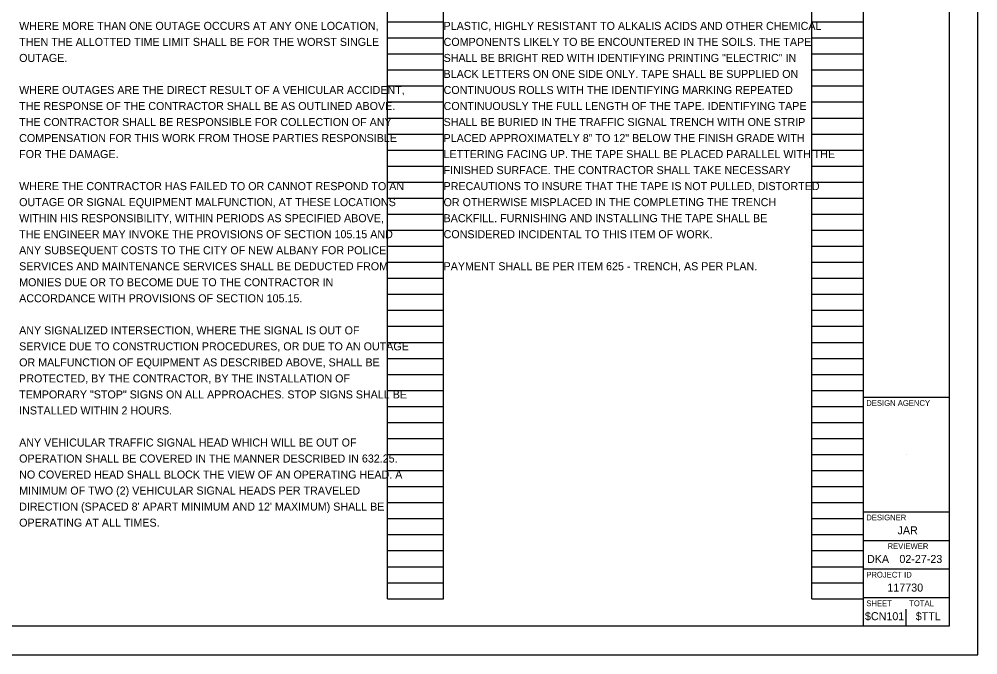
# Model space of a CAD drawing. Extents: x 0 to 34, y 0 to 22.
# Drawn here: x 17.24 to 34, y 0 to 11.11 of the extents above; entities that cross this region are included whole.
import ezdxf

# ---------------------------------------------------------------- set-up
doc = ezdxf.new("R2010")
doc.units = 0
for name, color, linetype in [('SH_Border', 7, 'Continuous'), ('SH_Cut_Line', 7, 'Continuous'), ('SH_Data', 7, 'Continuous'), ('SH_Text', 7, 'Continuous')]:
    doc.layers.add(name, color=color, linetype=linetype)

msp = doc.modelspace()

# ---------------------------------------------------------------- linework, layer by layer
at = {"layer": 'SH_Border'}
for p, q in [((32, 0.5), (32, 21.5)), ((32, 4.5), (33.5, 4.5)), ((32, 2.5), (33.5, 2.5)), ((32, 2), (33.5, 2)), ((32, 1.5), (33.5, 1.5)), ((32, 1), (33.5, 1))]:
    msp.add_line(p, q, dxfattribs=at)
msp.add_lwpolyline([(1.5, 21.5), (33.5, 21.5), (33.5, 0.5), (1.5, 0.5)], close=True, dxfattribs=at)
at = {"layer": 'SH_Cut_Line'}
msp.add_lwpolyline([(0, 0), (34, 0), (34, 22), (0, 22)], close=True, dxfattribs=at)
at = {"layer": 'SH_Data'}
for p, q in [((23.68, 0.98), (23.68, 21.14)), ((24.66, 0.98), (24.66, 21.14)), ((31.1, 0.98), (31.1, 21.14)), ((32, 0.98), (32, 21.14)), ((23.68, 11.06), (24.66, 11.06)), ((31.1, 11.06), (32, 11.06)), ((23.68, 10.78), (24.66, 10.78)), ((31.1, 10.78), (32, 10.78)), ((23.68, 10.5), (24.66, 10.5)), ((31.1, 10.5), (32, 10.5)), ((23.68, 10.22), (24.66, 10.22)), ((31.1, 10.22), (32, 10.22)), ((23.68, 9.94), (24.66, 9.94)), ((31.1, 9.94), (32, 9.94)), ((23.68, 9.66), (24.66, 9.66)), ((31.1, 9.66), (32, 9.66)), ((23.68, 9.38), (24.66, 9.38)), ((31.1, 9.38), (32, 9.38)), ((23.68, 9.1), (24.66, 9.1)), ((31.1, 9.1), (32, 9.1)), ((23.68, 8.82), (24.66, 8.82)), ((31.1, 8.82), (32, 8.82)), ((23.68, 8.54), (24.66, 8.54)), ((31.1, 8.54), (32, 8.54)), ((23.68, 8.26), (24.66, 8.26)), ((31.1, 8.26), (32, 8.26)), ((23.68, 7.98), (24.66, 7.98)), ((31.1, 7.98), (32, 7.98)), ((23.68, 7.7), (24.66, 7.7)), ((31.1, 7.7), (32, 7.7)), ((23.68, 7.42), (24.66, 7.42)), ((31.1, 7.42), (32, 7.42)), ((23.68, 7.14), (24.66, 7.14)), ((31.1, 7.14), (32, 7.14)), ((23.68, 6.86), (24.66, 6.86)), ((31.1, 6.86), (32, 6.86)), ((23.68, 6.58), (24.66, 6.58)), ((31.1, 6.58), (32, 6.58)), ((23.68, 6.3), (24.66, 6.3)), ((31.1, 6.3), (32, 6.3)), ((23.68, 6.02), (24.66, 6.02)), ((31.1, 6.02), (32, 6.02)), ((23.68, 5.74), (24.66, 5.74)), ((31.1, 5.74), (32, 5.74)), ((23.68, 5.46), (24.66, 5.46)), ((31.1, 5.46), (32, 5.46)), ((23.68, 5.18), (24.66, 5.18)), ((31.1, 5.18), (32, 5.18)), ((23.68, 4.9), (24.66, 4.9)), ((31.1, 4.9), (32, 4.9)), ((23.68, 4.62), (24.66, 4.62)), ((31.1, 4.62), (32, 4.62)), ((23.68, 4.34), (24.66, 4.34)), ((31.1, 4.34), (32, 4.34)), ((23.68, 4.06), (24.66, 4.06)), ((31.1, 4.06), (32, 4.06)), ((23.68, 3.78), (24.66, 3.78)), ((31.1, 3.78), (32, 3.78)), ((23.68, 3.5), (24.66, 3.5)), ((31.1, 3.5), (32, 3.5)), ((32.75, 3.5), (32.75, 3.5)), ((23.68, 3.22), (24.66, 3.22)), ((31.1, 3.22), (32, 3.22)), ((23.68, 2.94), (24.66, 2.94)), ((31.1, 2.94), (32, 2.94)), ((23.68, 2.66), (24.66, 2.66)), ((31.1, 2.66), (32, 2.66)), ((23.68, 2.38), (24.66, 2.38)), ((31.1, 2.38), (32, 2.38)), ((23.68, 2.1), (24.66, 2.1)), ((31.1, 2.1), (32, 2.1)), ((23.68, 1.82), (24.66, 1.82)), ((31.1, 1.82), (32, 1.82)), ((23.68, 1.54), (24.66, 1.54)), ((31.1, 1.54), (32, 1.54)), ((23.68, 1.26), (24.66, 1.26)), ((31.1, 1.26), (32, 1.26)), ((23.68, 0.98), (24.66, 0.98)), ((31.1, 0.98), (32, 0.98)), ((32.375, 0.675), (32.375, 0.675)), ((32.75, 0.5), (32.75, 0.8))]:
    msp.add_line(p, q, dxfattribs=at)

# ---------------------------------------------------------------- texts
for s, height, p in [('DESIGN AGENCY', 0.1, (32.05, 4.35)), ('DESIGNER', 0.1, (32.05, 2.35)), ('JAR', 0.14, (32.597, 2.105)), ('REVIEWER', 0.1, (32.422, 1.85)), ('DKA', 0.14, (32.063, 1.605)), ('02-27-23', 0.14, (32.629, 1.605)), ('PROJECT ID', 0.1, (32.05, 1.35)), ('117730', 0.14, (32.419, 1.105)), ('SHEET', 0.1, (32.05, 0.85)), ('TOTAL', 0.1, (32.8, 0.85)), ('$CN101', 0.14, (32.027, 0.605)), ('$TTL', 0.14, (32.915, 0.605))]:
    msp.add_text(s, height=height, dxfattribs=at).set_placement(p)
at = {"layer": 'SH_Text'}
for s, p in [('WHERE MORE THAN ONE OUTAGE OCCURS AT ANY ONE LOCATION, ', (17.24, 10.92)), ('PLASTIC, HIGHLY RESISTANT TO ALKALIS ACIDS AND OTHER CHEMICAL ', (24.66, 10.92)), ('THEN THE ALLOTTED TIME LIMIT SHALL BE FOR THE WORST SINGLE ', (17.24, 10.64)), ('COMPONENTS LIKELY TO BE ENCOUNTERED IN THE SOILS. THE TAPE ', (24.66, 10.64)), ('OUTAGE.', (17.24, 10.36)), ('SHALL BE BRIGHT RED WITH IDENTIFYING PRINTING "ELECTRIC" IN ', (24.66, 10.36)), ('BLACK LETTERS ON ONE SIDE ONLY. TAPE SHALL BE SUPPLIED ON ', (24.66, 10.08)), ('WHERE OUTAGES ARE THE DIRECT RESULT OF A VEHICULAR ACCIDENT, ', (17.24, 9.8)), ('CONTINUOUS ROLLS WITH THE IDENTIFYING MARKING REPEATED ', (24.66, 9.8)), ('THE RESPONSE OF THE CONTRACTOR SHALL BE AS OUTLINED ABOVE. ', (17.24, 9.52)), ('CONTINUOUSLY THE FULL LENGTH OF THE TAPE. IDENTIFYING TAPE ', (24.66, 9.52)), ('THE CONTRACTOR SHALL BE RESPONSIBLE FOR COLLECTION OF ANY ', (17.24, 9.24)), ('SHALL BE BURIED IN THE TRAFFIC SIGNAL TRENCH WITH ONE STRIP ', (24.66, 9.24)), ('COMPENSATION FOR THIS WORK FROM THOSE PARTIES RESPONSIBLE ', (17.24, 8.96)), ('PLACED APPROXIMATELY 8" TO 12" BELOW THE FINISH GRADE WITH ', (24.66, 8.96)), ('FOR THE DAMAGE.', (17.24, 8.68)), ('LETTERING FACING UP. THE TAPE SHALL BE PLACED PARALLEL WITH THE ', (24.66, 8.68)), ('FINISHED SURFACE. THE CONTRACTOR SHALL TAKE NECESSARY ', (24.66, 8.4)), ('WHERE THE CONTRACTOR HAS FAILED TO OR CANNOT RESPOND TO AN ', (17.24, 8.12)), ('PRECAUTIONS TO INSURE THAT THE TAPE IS NOT PULLED, DISTORTED ', (24.66, 8.12)), ('OUTAGE OR SIGNAL EQUIPMENT MALFUNCTION, AT THESE LOCATIONS ', (17.24, 7.84)), ('OR OTHERWISE MISPLACED IN THE COMPLETING THE TRENCH ', (24.66, 7.84)), ('WITHIN HIS RESPONSIBILITY, WITHIN PERIODS AS SPECIFIED ABOVE, ', (17.24, 7.56)), ('BACKFILL. FURNISHING AND INSTALLING THE TAPE SHALL BE ', (24.66, 7.56)), ('THE ENGINEER MAY INVOKE THE PROVISIONS OF SECTION 105.15 AND ', (17.24, 7.28)), ('CONSIDERED INCIDENTAL TO THIS ITEM OF WORK.', (24.66, 7.28)), ('ANY SUBSEQUENT COSTS TO THE CITY OF NEW ALBANY FOR POLICE ', (17.24, 7)), ('SERVICES AND MAINTENANCE SERVICES SHALL BE DEDUCTED FROM ', (17.24, 6.72)), ('PAYMENT SHALL BE PER ITEM 625 - TRENCH, AS PER PLAN.', (24.66, 6.72)), ('MONIES DUE OR TO BECOME DUE TO THE CONTRACTOR IN ', (17.24, 6.44)), ('ACCORDANCE WITH PROVISIONS OF SECTION 105.15.', (17.24, 6.16)), ('ANY SIGNALIZED INTERSECTION, WHERE THE SIGNAL IS OUT OF ', (17.24, 5.6)), ('SERVICE DUE TO CONSTRUCTION PROCEDURES, OR DUE TO AN OUTAGE ', (17.24, 5.32)), ('OR MALFUNCTION OF EQUIPMENT AS DESCRIBED ABOVE, SHALL BE ', (17.24, 5.04)), ('PROTECTED, BY THE CONTRACTOR, BY THE INSTALLATION OF ', (17.24, 4.76)), ('TEMPORARY "STOP" SIGNS ON ALL APPROACHES. STOP SIGNS SHALL BE ', (17.24, 4.48)), ('INSTALLED WITHIN 2 HOURS.', (17.24, 4.2)), ('ANY VEHICULAR TRAFFIC SIGNAL HEAD WHICH WILL BE OUT OF ', (17.24, 3.64)), ('OPERATION SHALL BE COVERED IN THE MANNER DESCRIBED IN 632.25. ', (17.24, 3.36)), ('NO COVERED HEAD SHALL BLOCK THE VIEW OF AN OPERATING HEAD. A ', (17.24, 3.08)), ('MINIMUM OF TWO (2) VEHICULAR SIGNAL HEADS PER TRAVELED ', (17.24, 2.8)), ("DIRECTION (SPACED 8' APART MINIMUM AND 12' MAXIMUM) SHALL BE ", (17.24, 2.52)), ('OPERATING AT ALL TIMES.', (17.24, 2.24))]:
    msp.add_text(s, height=0.14, dxfattribs=at).set_placement(p)

doc.saveas('drawing.dxf')
